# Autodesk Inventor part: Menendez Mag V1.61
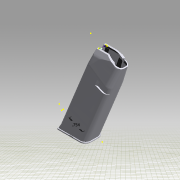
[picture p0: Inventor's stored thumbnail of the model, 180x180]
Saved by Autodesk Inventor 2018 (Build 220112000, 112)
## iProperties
Created: 2019-01
Part Number: Menendez Mag V1.61
Material: Nylon 6/6
Document SubType Name: Modeling
Designer: Ivan
Density: 1.13 g/cm^3
Appearance: Cool White
Sending System: Autodesk Inventor 2018
Preprocessor: ST-DEVELOPER v16.13
Title: D:\Downloads\Glock_Magazine v4 temp2.stp
Author: Ivan
Revision Number: ANY
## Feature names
1. Extrusion1
2. Extrusion2
3. Extrusion3
4. Extrusion4
5. Fillet1
6. Extrusion5
7. Extrusion7
8. Extrusion8
9. Extrusion9
10. Extrusion10
11. Extrusion11
12. Extrusion12
13. Extrusion13
14. Extrusion20
15. Extrusion21
16. Mirror2
17. Extrusion22
18. Extrusion23
19. Extrusion24
20. Mirror3
21. Extrusion25
22. Extrusion26
23. Extrusion27
24. Extrusion28
25. Extrusion29
26. Extrusion30
27. Extrusion31
28. Extrusion32
29. Extrusion33
30. Mirror4
31. Extrusion34
32. Extrusion36
33. Extrusion37
34. Extrusion38
35. Extrusion39
36. Mirror5
37. Extrusion41
38. Extrusion42
39. Extrusion43
40. Mirror6
41. Mirror7
42. Extrusion44
43. Loft1
44. Mirror8
45. Extrusion45
46. Extrusion46
47. Extrusion47
48. Extrusion48
49. Extrusion49
50. Extrusion50
51. Extrusion51
52. Extrusion52
53. Extrusion54
54. Extrusion55
55. Extrusion56
56. Mirror9
57. Extrusion57
58. Loft2
59. Mirror10
60. Mirror11
61. Extrusion58
62. Extrusion60
63. Mirror14
64. Extrusion61
65. Mirror15
66. Extrusion62
67. Mirror16
68. Extrusion63
69. Fillet3
70. Extrusion65
71. Mirror18
72. Extrusion66
73. Extrusion67
74. Mirror19
75. Fillet20
76. Sweep3
77. Extrusion81
78. Extrusion82
79. Mirror30
80. Extrusion84
81. Mirror32
82. Extrusion85
83. Extrusion86
84. Extrusion87
85. Fillet21
86. Mirror33
87. Mirror34
88. Extrusion88
89. Mirror35
90. Extrusion89
91. Chamfer1
92. Extrusion90
93. Extrusion91
94. Mirror36
95. Extrusion92
96. Chamfer2
97. Chamfer3
98. Extrusion93
99. Mirror37
100. Fillet23
101. Chamfer4
102. Fillet24
103. Fillet25
104. Fillet26
105. Mirror39
106. Extrusion94
107. Mirror40
108. Fillet27
109. Extrusion95
110. Mirror41
111. Extrusion96
112. Mirror42
113. Extrusion97
114. Mirror43
115. Extrusion98
116. Extrusion99
117. Extrusion100
118. Extrusion101
119. Extrusion102
120. Mirror44
121. Extrusion104
122. Extrusion105
123. Mirror46
124. Extrusion106
125. Mirror47
126. Extrusion127
127. Extrusion128
128. Extrusion129
129. Extrusion130
130. Mirror50
131. Extrusion132
132. Extrusion133
133. Mirror52
134. Extrusion134
135. Mirror53
136. Extrusion135
137. Extrusion136
138. Extrusion137
139. Mirror54
140. Extrusion138
141. Extrusion139
142. Extrusion140
143. Extrusion141
144. Mirror55
145. Extrusion143
146. Mirror56
147. Extrusion144
148. Extrusion146
149. Mirror58
150. Extrusion147
151. Mirror59
152. Fillet38
153. Extrusion148
154. Extrusion150
155. Mirror60
156. Extrusion153
157. Mirror61
158. Extrusion154
159. Extrusion155
160. Extrusion156
161. Fillet39
162. Fillet40
163. Extrusion158
164. Extrusion159
165. Mirror64
166. Fillet44
167. Extrusion160
168. Fillet45
169. Mirror65
170. Mirror66
171. Solid1
## Parameters: d0 = 9.75 mm, d5 = 10.15 mm, d7 = 10.3 mm, d9 = 0.4064 mm, d10 = 25.4 mm, d11 = 0, d12 = 25.4 mm, d13 = 0, d14 = 2.54 mm, d15 = 0, d16 = 0.4064 mm, d17 = 0, d18 = 0.254 mm, d19 = 50.8 mm, d20 = 0, d21 = 1.905 mm, d24 = 50.8 mm, d25 = 0, d26 = 50.8 mm, d27 = 0, d28 = 2.54 mm, d29 = 0, d30 = 2.54 mm, d31 = 0, d32 = 2.54 mm, d33 = 0, d34 = 2.54 mm, d35 = 0, d36 = 1 mm, d37 = 0, d39 = -21 deg, d57 = 1.5 mm, d58 = 0, d59 = 4 mm, d60 = 0, d61 = 4 mm, d62 = 0, d63 = 4 mm, d64 = 0, d65 = 8 mm, d66 = 0, d67 = 8 mm, d68 = 0, d69 = 2 mm, d70 = 0, d71 = 2 mm, d72 = 0, d73 = 2 mm, d74 = 0, d75 = 2 mm, d76 = 0, d77 = 2 mm, d78 = 0, d79 = -8.11 mm, d80 = 2 mm, d81 = 0, d82 = 2 mm, d83 = 0, d84 = 2 mm, d85 = 0, d86 = 2 mm, d87 = 0, d90 = 1 mm, d91 = 0, d92 = 2 mm, d93 = 0, d94 = 2 mm, d95 = 0, d96 = 2 mm, d97 = 0, d100 = 2 mm, d101 = 0, d102 = 2 mm, d103 = 0, d104 = 2 mm, d105 = 0, d106 = 2 mm, d107 = 0, d108 = 0, d109 = 90 deg, d110 = 0, d111 = 90 deg, d112 = 90 deg, d113 = 0.127 mm, d114 = 0.5 mm, d115 = 0, d116 = 0.5 mm, d117 = 0, d118 = 0.142 mm, d119 = 0, d120 = 0.142 mm, d121 = 0, d122 = 0.142 mm, d123 = 0, d124 = 0.142 mm, d125 = 0, d126 = 0.142 mm, d127 = 0, d128 = 0.142 mm, d129 = 0, d132 = 0.142 mm, d133 = 0, d134 = 0.142 mm, d135 = 0, d136 = 4.3053 mm, d137 = 2 mm, d138 = 0, d139 = 1 mm, d140 = 0, d141 = -2.5 mm, d142 = 0, d143 = 90 deg, d144 = 0, d145 = 90 deg, d146 = 0.05 mm, d147 = 0, d153 = -0.19199 mm, d166 = 25.4 mm, d167 = 0, d168 = 90 deg, d169 = 25.4 mm, d170 = 0, d171 = 90 deg, d173 = 304.8 mm, d174 = 0, d175 = 304.8 mm, d176 = 0, d177 = 2.54 mm, d184 = 0.254 mm, d185 = 304.8 mm, d186 = 0, d187 = 90 deg, d188 = 12.7 mm, d189 = 0, d190 = 12.7 mm, d191 = 0, d237 = 90 deg, d238 = 0.2032 mm, d240 = 2.54 mm, d241 = 0, d242 = 0, d245 = 1.27 mm, d246 = 0, d247 = 50.8 mm, d248 = 0, d251 = 0.381 mm, d252 = 5.08 mm, d253 = 0.1905 mm, d254 = 0.762 mm, d255 = 0.254 mm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
